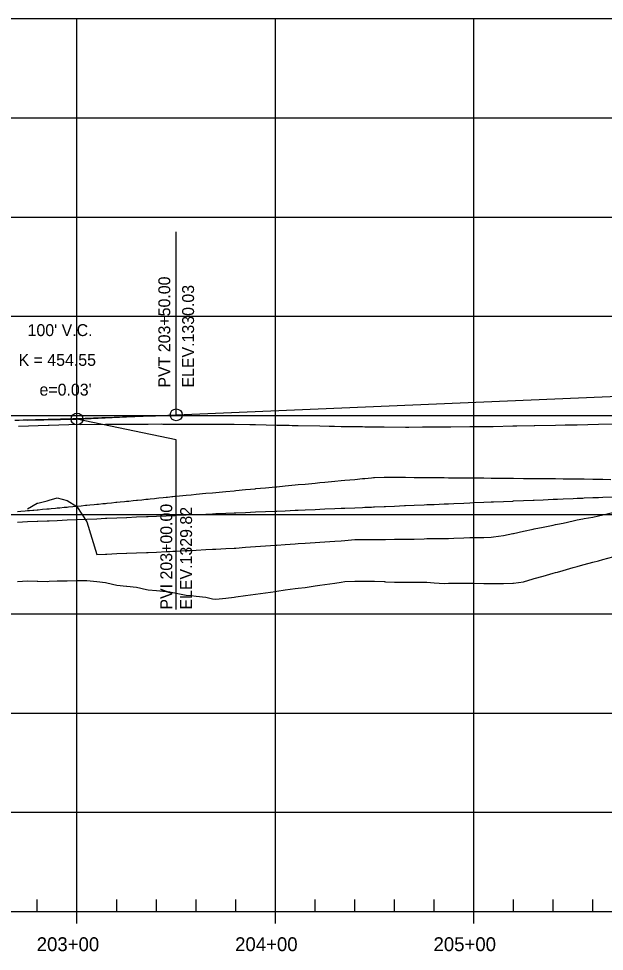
# Model space of a CAD drawing. Extents: x 1371206 to 1374178, y 379328 to 381511.
# Drawn here: x 1371515.2 to 1371810.4, y 379328.3 to 379798.4 of the extents above; entities that cross this region are included whole.
import ezdxf

# ---------------------------------------------------------------- set-up
doc = ezdxf.new("R2010")
doc.units = 0
for name, color, linetype in [('30', 7, 'Continuous'), ('37', 7, 'Continuous'), ('R_Exist Surface', 7, 'Continuous'), ('R_Profile Work Left', 7, 'Continuous'), ('R_Profile Work Right', 7, 'Continuous'), ('R_Vert Alg', 7, 'Continuous'), ('R_Vert Alg Annot', 7, 'Continuous')]:
    doc.layers.add(name, color=color, linetype=linetype)

msp = doc.modelspace()

# ---------------------------------------------------------------- linework, layer by layer
at = {"layer": '37'}
for p, q in [((1371244.63, 379798.35), (1374144.63, 379798.35)), ((1371244.63, 379798.35), (1374144.63, 379798.35)), ((1371544.63, 379348.35), (1371544.63, 379798.35)), ((1371644.63, 379348.35), (1371644.63, 379798.35)), ((1371744.63, 379348.35), (1371744.63, 379798.35)), ((1371244.63, 379748.35), (1374144.63, 379748.35)), ((1371244.63, 379698.35), (1374144.63, 379698.35)), ((1371244.63, 379648.35), (1374144.63, 379648.35)), ((1371244.63, 379598.35), (1372944.63, 379598.35)), ((1371244.63, 379598.35), (1374144.63, 379598.35)), ((1371244.63, 379548.35), (1374144.63, 379548.35)), ((1371244.63, 379498.35), (1374144.63, 379498.35)), ((1371244.63, 379448.35), (1374144.63, 379448.35)), ((1371244.63, 379398.35), (1374144.63, 379398.35)), ((1371524.63, 379348.35), (1371524.63, 379354.35)), ((1371564.63, 379348.35), (1371564.63, 379354.35)), ((1371584.63, 379348.35), (1371584.63, 379354.35)), ((1371604.63, 379348.35), (1371604.63, 379354.35)), ((1371624.63, 379348.35), (1371624.63, 379354.35)), ((1371664.63, 379348.35), (1371664.63, 379354.35)), ((1371684.63, 379348.35), (1371684.63, 379354.35)), ((1371704.63, 379348.35), (1371704.63, 379354.35)), ((1371724.63, 379348.35), (1371724.63, 379354.35)), ((1371764.63, 379348.35), (1371764.63, 379354.35)), ((1371784.63, 379348.35), (1371784.63, 379354.35)), ((1371804.63, 379348.35), (1371804.63, 379354.35)), ((1371244.63, 379348.35), (1374144.63, 379348.35)), ((1371544.63, 379342.35), (1371544.63, 379348.35)), ((1371644.63, 379342.35), (1371644.63, 379348.35)), ((1371744.63, 379342.35), (1371744.63, 379348.35))]:
    msp.add_line(p, q, dxfattribs=at)
at = {"layer": 'R_Exist Surface'}
msp.add_lwpolyline([(1371515.07, 379592.93), (1371530.08, 379593.4), (1371530.53, 379593.42), (1371545.4, 379593.89), (1371546.24, 379593.87), (1371558.92, 379593.92), (1371566.67, 379593.96), (1371569.73, 379593.97), (1371580.54, 379594.02), (1371587.17, 379594.05), (1371587.93, 379594.04), (1371591.35, 379594.03), (1371602.15, 379593.99), (1371609.63, 379593.97), (1371609.84, 379593.96), (1371610.03, 379593.96), (1371612.96, 379593.95), (1371615.77, 379593.95), (1371623.77, 379593.88), (1371631.77, 379593.79), (1371634.57, 379593.74), (1371645.38, 379593.52), (1371651.54, 379593.39), (1371653.11, 379593.35), (1371656.19, 379593.29), (1371666.99, 379593.05), (1371671.72, 379592.95), (1371674.48, 379592.88), (1371677.8, 379592.84), (1371688.61, 379592.71), (1371689.67, 379592.69), (1371693.24, 379592.69), (1371697.31, 379592.68), (1371699.41, 379592.66), (1371710.22, 379592.53), (1371711.93, 379592.5), (1371718.74, 379592.56), (1371721.03, 379592.58), (1371731.83, 379592.68), (1371733.13, 379592.7), (1371742.64, 379592.78), (1371744.83, 379592.8), (1371753.45, 379592.85), (1371754.4, 379592.85), (1371764.25, 379593.09), (1371766.35, 379593.14), (1371775.06, 379593.24), (1371775.32, 379593.24), (1371785.87, 379593.51), (1371790.63, 379593.62), (1371796.19, 379593.69), (1371796.67, 379593.7), (1371807.48, 379593.89), (1371816.35, 379594.05)], dxfattribs=at)
at = {"layer": 'R_Profile Work Left'}
for points in [[(1371514.63, 379549.92), (1371516.37, 379550.08), (1371518.54, 379550.27), (1371519.63, 379550.37), (1371520.72, 379550.47), (1371522.35, 379550.61), (1371522.89, 379550.66), (1371524.63, 379550.82), (1371524.83, 379550.84), (1371525.07, 379550.86), (1371527.24, 379551.05), (1371527.25, 379551.06), (1371529.41, 379551.25), (1371529.63, 379551.27), (1371530.63, 379551.37), (1371531.59, 379551.45), (1371533.76, 379551.65), (1371534.63, 379551.73), (1371535.93, 379551.86), (1371538.11, 379552.06), (1371539.63, 379552.2), (1371540.28, 379552.26), (1371542.46, 379552.47), (1371544.63, 379552.67), (1371546.8, 379552.88), (1371548.98, 379553.09), (1371549.63, 379553.15), (1371551.15, 379553.3), (1371553.33, 379553.51), (1371554.63, 379553.64), (1371555.5, 379553.72), (1371557.67, 379553.93), (1371558.92, 379554.06), (1371559.63, 379554.13), (1371559.85, 379554.15), (1371562.02, 379554.36), (1371564.2, 379554.58), (1371564.63, 379554.62), (1371566.37, 379554.79), (1371568.54, 379555.01), (1371569.63, 379555.12), (1371569.73, 379555.13), (1371570.72, 379555.23), (1371572.89, 379555.45), (1371574.63, 379555.63), (1371575.07, 379555.67), (1371577.24, 379555.89), (1371579.41, 379556.12), (1371579.63, 379556.14), (1371580.54, 379556.23), (1371581.59, 379556.34), (1371583.76, 379556.57), (1371584.63, 379556.66), (1371585.93, 379556.79), (1371588.11, 379557.02), (1371589.63, 379557.18), (1371590.28, 379557.25), (1371591.35, 379557.36), (1371592.46, 379557.48), (1371593.01, 379557.54), (1371593.99, 379557.66), (1371594.01, 379557.66), (1371594.63, 379557.72), (1371599.63, 379558.19), (1371602.15, 379558.42), (1371604.63, 379558.66), (1371609.63, 379559.12), (1371612.96, 379559.43), (1371614.63, 379559.59), (1371619.63, 379560.06), (1371623.77, 379560.44), (1371624.63, 379560.52), (1371629.63, 379560.99), (1371634.57, 379561.45), (1371634.63, 379561.46), (1371639.63, 379561.93), (1371644.63, 379562.39), (1371645.38, 379562.46), (1371649.63, 379562.86), (1371654.63, 379563.33), (1371656.19, 379563.47), (1371659.63, 379563.79), (1371664.63, 379564.26), (1371666.99, 379564.48), (1371669.63, 379564.73), (1371674.63, 379565.19), (1371677.8, 379565.49), (1371679.63, 379565.66), (1371684.63, 379566.13), (1371688.61, 379566.5), (1371689.63, 379566.6), (1371693.01, 379566.91), (1371694.01, 379567.01), (1371694.63, 379567.03), (1371699.41, 379567.23), (1371699.63, 379567.24), (1371700.17, 379567.27), (1371704.63, 379567.23), (1371709.63, 379567.18), (1371710.22, 379567.18), (1371714.63, 379567.14), (1371719.63, 379567.1), (1371721.03, 379567.08), (1371724.63, 379567.05), (1371729.63, 379567.01), (1371731.83, 379566.99), (1371734.63, 379566.96), (1371739.63, 379566.92), (1371742.64, 379566.89), (1371744.63, 379566.88), (1371749.63, 379566.83), (1371753.45, 379566.8), (1371754.63, 379566.79), (1371759.63, 379566.74), (1371764.25, 379566.7), (1371764.63, 379566.7), (1371769.63, 379566.66), (1371774.63, 379566.61), (1371775.06, 379566.61), (1371779.63, 379566.57), (1371784.63, 379566.52), (1371785.87, 379566.51), (1371789.63, 379566.48), (1371794.63, 379566.44), (1371796.67, 379566.42), (1371799.63, 379566.39), (1371800.17, 379566.39), (1371804.63, 379566.29), (1371807.48, 379566.23), (1371809.63, 379566.18), (1371813.63, 379566.1)], [(1371514.63, 379514.65), (1371519.63, 379514.97), (1371524.63, 379514.82), (1371524.83, 379514.81), (1371529.63, 379514.66), (1371530.63, 379514.76), (1371534.63, 379515.08), (1371539.63, 379514.93), (1371544.63, 379515.12), (1371549.63, 379515.1), (1371554.63, 379514.65), (1371558.92, 379514.23), (1371559.63, 379514.02), (1371564.63, 379512.82), (1371569.63, 379512.35), (1371569.73, 379512.34), (1371574.63, 379511.88), (1371579.63, 379510.66), (1371580.54, 379510.44), (1371584.63, 379510.05), (1371589.63, 379509.58), (1371591.35, 379509.41), (1371593.01, 379509.19), (1371593.99, 379508.92), (1371594.01, 379508.92), (1371594.63, 379508.74), (1371599.63, 379507.79), (1371602.15, 379507.55), (1371604.63, 379507.32), (1371609.63, 379506.84), (1371612.96, 379505.95), (1371614.63, 379505.69), (1371619.63, 379506.31), (1371623.77, 379506.83), (1371624.63, 379506.93), (1371629.63, 379507.67), (1371634.57, 379508.34), (1371634.63, 379508.35), (1371639.63, 379508.98), (1371644.63, 379509.67), (1371645.38, 379509.79), (1371649.63, 379510.43), (1371654.63, 379511.07), (1371656.19, 379511.27), (1371659.63, 379511.72), (1371664.63, 379512.53), (1371666.99, 379512.84), (1371669.63, 379513.19), (1371674.63, 379513.84), (1371677.8, 379514.29), (1371679.63, 379514.6), (1371684.63, 379514.89), (1371688.61, 379514.86), (1371689.63, 379514.85), (1371693.01, 379514.83), (1371694.01, 379514.82), (1371694.63, 379514.82), (1371699.41, 379514.63), (1371699.63, 379514.61), (1371700.17, 379514.57), (1371704.63, 379514.36), (1371709.63, 379514.37), (1371710.22, 379514.37), (1371714.63, 379514.38), (1371719.63, 379514.36), (1371721.03, 379514.26), (1371724.63, 379514.02), (1371729.63, 379513.73), (1371731.83, 379513.74), (1371734.63, 379513.76), (1371739.63, 379513.8), (1371742.64, 379513.82), (1371744.63, 379513.84), (1371749.63, 379513.64), (1371753.45, 379513.64), (1371754.63, 379513.66), (1371759.63, 379513.71), (1371764.25, 379513.77), (1371764.63, 379513.77), (1371769.63, 379514.49), (1371774.63, 379516.06), (1371775.06, 379516.17), (1371779.63, 379517.43), (1371784.63, 379518.8), (1371785.87, 379519.14), (1371786.76, 379519.38), (1371789.63, 379520.17), (1371794.63, 379521.72), (1371796.67, 379522.27), (1371799.63, 379523.06), (1371800.17, 379523.2), (1371804.63, 379524.4), (1371807.48, 379525.16), (1371809.63, 379525.74), (1371814.63, 379527.11)]]:
    msp.add_lwpolyline(points, dxfattribs=at)
at = {"layer": 'R_Profile Work Right'}
for points in [[(1371514.63, 379544.63), (1371519.63, 379544.85), (1371524.63, 379545.06), (1371524.83, 379545.07), (1371529.63, 379545.27), (1371530.63, 379545.31), (1371534.63, 379545.48), (1371539.63, 379545.69), (1371544.63, 379545.91), (1371549.63, 379546.12), (1371554.63, 379546.33), (1371558.92, 379546.51), (1371559.63, 379546.54), (1371564.63, 379546.76), (1371569.63, 379546.97), (1371569.73, 379546.97), (1371574.63, 379547.18), (1371579.63, 379547.39), (1371580.54, 379547.43), (1371584.63, 379547.6), (1371589.63, 379547.82), (1371591.35, 379547.89), (1371593.01, 379547.96), (1371593.99, 379548), (1371594.01, 379548), (1371594.63, 379548.03), (1371599.63, 379548.24), (1371602.15, 379548.35), (1371604.63, 379548.45), (1371609.63, 379548.67), (1371612.96, 379548.81), (1371614.63, 379548.88), (1371619.63, 379549.09), (1371623.77, 379549.27), (1371624.63, 379549.3), (1371629.63, 379549.51), (1371634.57, 379549.72), (1371634.63, 379549.73), (1371639.63, 379549.94), (1371644.63, 379550.15), (1371645.38, 379550.18), (1371649.63, 379550.36), (1371654.63, 379550.58), (1371656.19, 379550.64), (1371659.63, 379550.79), (1371664.63, 379551), (1371666.99, 379551.1), (1371669.63, 379551.21), (1371674.63, 379551.42), (1371677.8, 379551.56), (1371679.63, 379551.64), (1371684.63, 379551.85), (1371688.61, 379552.02), (1371689.63, 379552.06), (1371693.01, 379552.2), (1371694.01, 379552.25), (1371694.63, 379552.27), (1371699.41, 379552.48), (1371699.63, 379552.49), (1371700.17, 379552.51), (1371704.63, 379552.7), (1371709.63, 379552.91), (1371710.22, 379552.94), (1371714.63, 379553.12), (1371719.63, 379553.33), (1371721.03, 379553.39), (1371724.63, 379553.55), (1371729.63, 379553.76), (1371731.83, 379553.85), (1371734.63, 379553.97), (1371739.63, 379554.18), (1371742.64, 379554.31), (1371744.63, 379554.4), (1371749.63, 379554.61), (1371753.45, 379554.77), (1371754.63, 379554.82), (1371759.63, 379555.03), (1371764.25, 379555.23), (1371764.63, 379555.24), (1371769.63, 379555.46), (1371774.63, 379555.67), (1371775.06, 379555.69), (1371779.63, 379555.88), (1371784.63, 379556.09), (1371785.87, 379556.15), (1371786.76, 379556.18), (1371789.63, 379556.31), (1371794.63, 379556.52), (1371796.67, 379556.6), (1371799.63, 379556.73), (1371800.17, 379556.75), (1371804.63, 379556.94), (1371807.48, 379557.06), (1371809.63, 379557.15), (1371814.63, 379557.37)], [(1371519.63, 379551.32), (1371524.63, 379554.08), (1371524.83, 379554.13), (1371529.63, 379555.32), (1371530.63, 379555.62), (1371534.63, 379556.82), (1371539.63, 379555.43), (1371544.63, 379552.53), (1371549.63, 379544.66)], [(1371549.63, 379544.66), (1371554.63, 379528.27), (1371558.92, 379528.46), (1371559.63, 379528.49), (1371564.63, 379528.71), (1371569.63, 379528.94), (1371569.73, 379528.94), (1371574.63, 379529.05), (1371579.63, 379529.27), (1371580.54, 379529.31), (1371584.63, 379529.49), (1371589.63, 379529.72), (1371591.35, 379529.85), (1371593.01, 379529.93), (1371593.99, 379529.97), (1371594.01, 379529.98), (1371594.63, 379530), (1371599.63, 379530.23), (1371602.15, 379530.35), (1371604.63, 379530.46), (1371609.63, 379530.78), (1371612.96, 379530.94), (1371614.63, 379531.02), (1371619.63, 379531.26), (1371623.77, 379531.46), (1371624.63, 379531.51), (1371629.63, 379531.92), (1371634.57, 379532.27), (1371634.63, 379532.28), (1371639.63, 379532.64), (1371644.63, 379532.94), (1371645.38, 379533), (1371649.63, 379533.31), (1371654.63, 379533.68), (1371656.19, 379533.79), (1371659.63, 379533.98), (1371664.63, 379534.35), (1371666.99, 379534.53), (1371669.63, 379534.72), (1371674.63, 379535.01), (1371677.8, 379535.24), (1371679.63, 379535.38), (1371684.63, 379535.75), (1371688.61, 379535.79), (1371689.63, 379535.79), (1371693.01, 379535.8), (1371694.01, 379535.8), (1371694.63, 379535.8), (1371699.41, 379535.81), (1371699.63, 379535.82), (1371700.17, 379535.82), (1371704.63, 379536), (1371709.63, 379536.03), (1371710.22, 379536.03), (1371714.63, 379536.06), (1371719.63, 379536.1), (1371721.03, 379536.27), (1371724.63, 379536.34), (1371729.63, 379536.39), (1371731.83, 379536.41), (1371734.63, 379536.44), (1371739.63, 379536.74), (1371742.64, 379536.79), (1371744.63, 379536.82), (1371749.63, 379536.89), (1371753.45, 379536.95), (1371754.63, 379537.1), (1371759.63, 379537.82), (1371764.25, 379538.83), (1371764.63, 379538.91), (1371769.63, 379540), (1371774.63, 379541.1), (1371775.06, 379541.19), (1371779.63, 379542.04), (1371784.63, 379543.04), (1371785.87, 379543.31), (1371786.76, 379543.51), (1371789.63, 379544.14), (1371794.63, 379545.24), (1371796.67, 379545.69), (1371799.63, 379546.29), (1371800.17, 379546.37), (1371804.63, 379547.16), (1371807.48, 379547.79), (1371809.63, 379548.27), (1371814.63, 379549.37)]]:
    msp.add_lwpolyline(points, dxfattribs=at)
at = {"layer": 'R_Vert Alg'}
for p, q in [((1371594.63, 379598.67), (1372369.63, 379631.53)), ((1371519.63, 379596.06), (1371544.63, 379596.55)), ((1371544.63, 379596.55), (1371569.63, 379597.61))]:
    msp.add_line(p, q, dxfattribs=at)
msp.add_lwpolyline([(1371513.38, 379595.98), (1371515.46, 379596.03), (1371517.55, 379596.08), (1371519.63, 379596.13), (1371521.71, 379596.19), (1371523.8, 379596.24), (1371525.88, 379596.3), (1371527.96, 379596.35), (1371530.05, 379596.41), (1371532.13, 379596.47), (1371534.21, 379596.53), (1371536.3, 379596.59), (1371538.38, 379596.65), (1371540.46, 379596.71), (1371542.55, 379596.77), (1371546.71, 379596.9), (1371548.8, 379596.97), (1371550.88, 379597.03), (1371552.96, 379597.1), (1371555.05, 379597.17), (1371557.13, 379597.24), (1371559.21, 379597.31), (1371561.3, 379597.38), (1371563.38, 379597.46), (1371565.46, 379597.53), (1371567.55, 379597.61), (1371569.63, 379597.68), (1371571.71, 379597.76), (1371573.8, 379597.84), (1371575.88, 379597.92), (1371577.96, 379598), (1371580.05, 379598.08), (1371582.13, 379598.16), (1371584.21, 379598.24), (1371586.3, 379598.33), (1371588.38, 379598.41), (1371590.46, 379598.5), (1371592.55, 379598.58), (1371594.63, 379598.67)], dxfattribs=at)
for centre in [(1371594.63, 379598.67), (1371544.63, 379596.55)]:
    msp.add_circle(centre, 3, dxfattribs=at)
at = {"layer": 'R_Vert Alg Annot'}
msp.add_line((1371594.63, 379598.67), (1371594.63, 379690.98), dxfattribs=at)
msp.add_lwpolyline([(1371594.63, 379500.5), (1371594.63, 379586.07), (1371544.63, 379596.55)], dxfattribs=at)

# ---------------------------------------------------------------- texts
at = {"layer": '30'}
for s, p in [('203+00', (1371524.32, 379328.35)), ('204+00', (1371624.32, 379328.35)), ('205+00', (1371724.32, 379328.35))]:
    msp.add_text(s, height=7, dxfattribs=at).set_placement(p)
at = {"layer": 'R_Vert Alg Annot'}
for s, p in [('PVT 203+50.00', (1371591.63, 379612.4)), ('ELEV.1330.03', (1371603.63, 379612.4)), ('PVI 203+00.00', (1371592.63, 379500.5)), ('ELEV.1329.82', (1371602.63, 379500.5))]:
    msp.add_text(s, height=6, rotation=90, dxfattribs=at).set_placement(p)
for s, p in [("100' V.C.", (1371519.73, 379638.36)), ('K = 454.55', (1371515.17, 379623.36)), ("e=0.03'", (1371525.73, 379608.36))]:
    msp.add_text(s, height=6, dxfattribs=at).set_placement(p)

doc.saveas('drawing.dxf')
